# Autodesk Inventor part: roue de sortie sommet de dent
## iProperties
Shininess: 64.0
Length Units: 11269
Angle Units: 11279
Time Units: 11290
Mass Units: 11283
Length Display Precision: 3
Angle Display Precision: 2
Compacted: True
Part Number: roue de sortie sommet de dent
Document SubType Name: Modeling
Created: 2004-09
Material: Par défaut
Designer: Administrateur
Density: 1 g/cm^3
Density: 0.0
Volumn: 0.0
Area: 0.0
PropertySet Name: Model Information
Control State: 0
Master: False
Checked Out: False
Author: Administrateur
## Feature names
1. Extrusion1
